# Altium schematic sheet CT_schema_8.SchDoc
size 281 x 153 mm
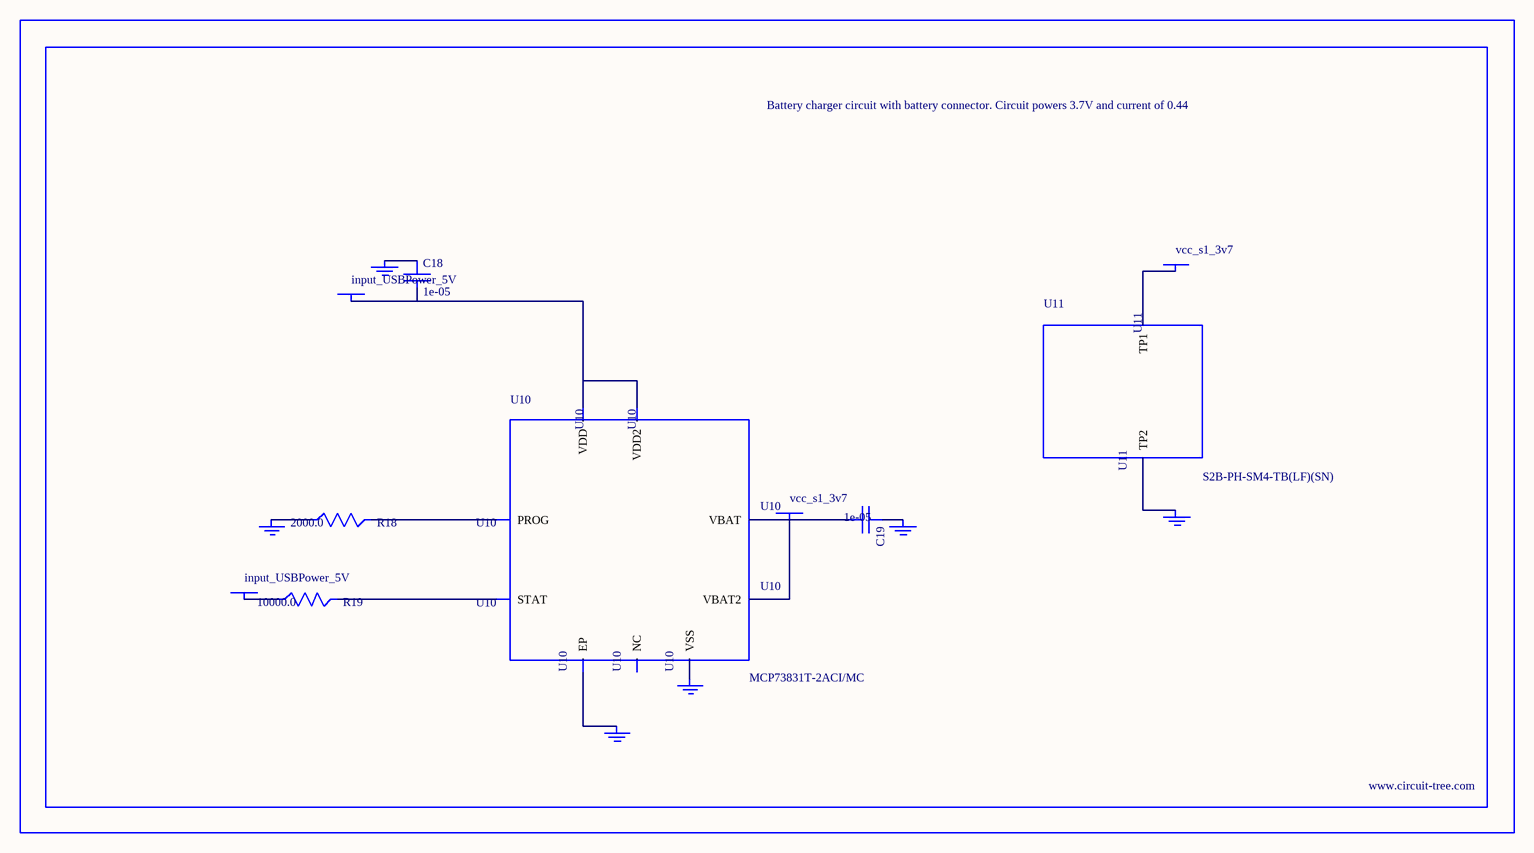
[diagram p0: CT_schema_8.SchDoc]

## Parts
BORDER7  (no value)
C18  1e-05  [C1206]
C19  1e-05  [C1206]
GND_INSTANCE_7_0  (no value)
GND_INSTANCE_7_1  (no value)
GND_INSTANCE_7_2  (no value)
GND_INSTANCE_7_3  (no value)
GND_INSTANCE_7_4  (no value)
GND_INSTANCE_7_5  (no value)
POWER_INSTANCE_7_0  input_USBPower_5V
POWER_INSTANCE_7_1  input_USBPower_5V
POWER_INSTANCE_7_2  vcc_s1_3v7
POWER_INSTANCE_7_3  vcc_s1_3v7
R18  2000.0  [R0603]
R19  10000.0  [R0603]
U10  MCP73831T-2ACI/MC  [DFN8_2X3MC]
U11  S2B-PH-SM4-TB(LF)(SN)  [JST-2-SMD]

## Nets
NetC18_1: C18.1 GND_INSTANCE_7_0.0(GND)
NetC18_2: C18.2 POWER_INSTANCE_7_0.0(PWR) U10.1(VDD) U10.2(VDD2)
NetC19_1: C19.1 GND_INSTANCE_7_1.0(GND)
NetC19_2: C19.2 POWER_INSTANCE_7_2.0(PWR) U10.3(VBAT) U10.4(VBAT2)
NetGND_INSTANCE_7_2_0: GND_INSTANCE_7_2.0(GND) R18.1
NetGND_INSTANCE_7_3_0: GND_INSTANCE_7_3.0(GND) U10.9(EP)
NetGND_INSTANCE_7_4_0: GND_INSTANCE_7_4.0(GND) U10.6(VSS)
NetGND_INSTANCE_7_5_0: GND_INSTANCE_7_5.0(GND) U11.2(TP2)
NetPOWER_INSTANCE_7_1_0: POWER_INSTANCE_7_1.0(PWR) R19.1
NetPOWER_INSTANCE_7_3_0: POWER_INSTANCE_7_3.0(PWR) U11.1(TP1)
NetR18_2: R18.2 U10.8(PROG)
NetR19_2: R19.2 U10.5(STAT)

Not connected (* = marked no-connect by the designer): U10 7(NC)

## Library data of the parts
BORDER7 = BORDER_PAGE7
C18 C19 = C1206C106K3RACTU
GND_INSTANCE_7_0-GND_INSTANCE_7_5 = GND
POWER_INSTANCE_7_0-POWER_INSTANCE_7_3 = PWR
R18 = RC0603JR-072KL
R19 = RC0603JR-0710KL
